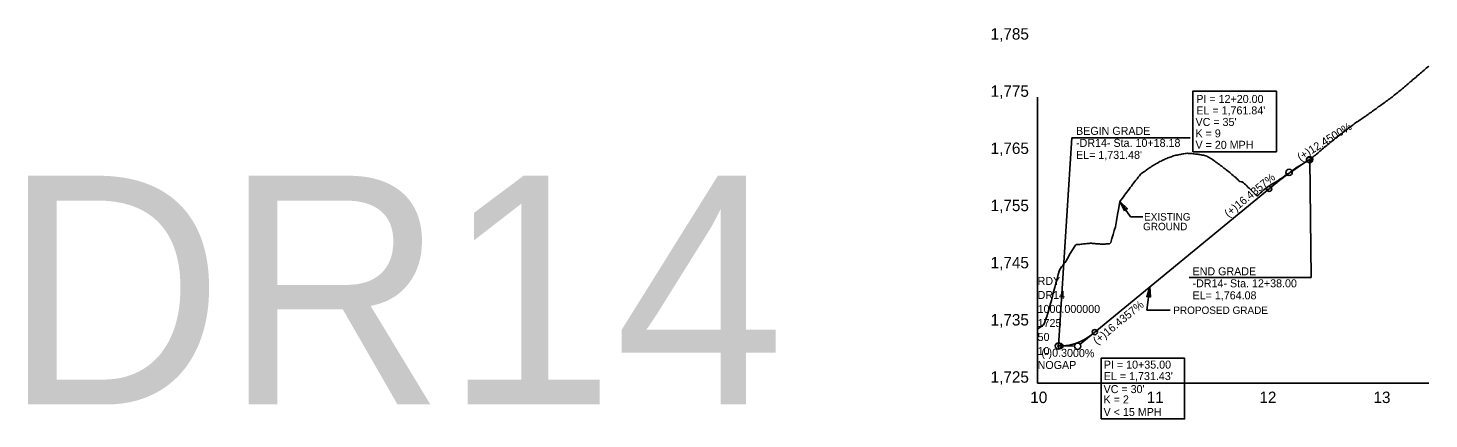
# Model space of a CAD drawing. Extents: x 498575 to 532350, y 405181 to 484585.
# Drawn here: x 526401 to 527626, y 452312 to 452654 of the extents above; entities that cross this region are included whole.
import ezdxf

# ---------------------------------------------------------------- set-up
doc = ezdxf.new("R2010")
doc.units = 0
for name, color, linetype in [('Exist Profile Cell', 7, 'Continuous'), ('Exist Vertical Profile Ground Line', 7, 'Continuous'), ('Exist Vertical Profile Horizontal Axis Label Major', 7, 'Continuous'), ('Exist Vertical Profile Vertical Axis Label', 7, 'Continuous'), ('Prop Grid Mask', 7, 'Continuous'), ('Prop PFL Text', 7, 'Continuous'), ('Prop Vertical Profile Curve Label', 7, 'Continuous'), ('Prop Vertical Profile Grade', 7, 'Continuous'), ('Prop Vertical Profile Grade Label', 7, 'Continuous'), ('Prop VPI Label', 7, 'Continuous'), ('Scratch_Level_7', 7, 'Continuous')]:
    doc.layers.add(name, color=color, linetype=linetype)

msp = doc.modelspace()

# ---------------------------------------------------------------- linework, layer by layer
at = {"layer": 'Exist Profile Cell'}
for q in [(527283.8, 452593.4), (527626.1, 452343.4), (527283.8, 452343.4)]:
    msp.add_line((527283.8, 452343.4), q, dxfattribs=at)
at = {"layer": 'Exist Vertical Profile Ground Line'}
for points in [[(527583.8, 452586.2), (527584.8, 452586.9), (527585.8, 452587.6), (527586.8, 452588.4), (527587.8, 452589.1), (527588.8, 452589.8), (527589.8, 452590.5), (527590.8, 452591.2), (527591.8, 452591.9), (527592.8, 452592.7), (527593.8, 452593.5), (527594.8, 452594.3), (527595.8, 452595.1), (527596.8, 452595.9), (527597.8, 452596.7), (527598.8, 452597.5), (527599.8, 452598.3), (527600.8, 452599.1), (527601.8, 452599.9), (527602.8, 452600.8), (527603.8, 452601.6), (527604.8, 452602.4), (527605.8, 452603.2), (527606.8, 452604.1), (527607.8, 452605), (527608.8, 452605.8), (527609.8, 452606.7), (527610.8, 452607.5), (527611.8, 452608.4), (527612.8, 452609.3), (527613.8, 452610.1), (527614.8, 452611), (527615.8, 452611.9), (527616.8, 452612.7), (527617.8, 452613.6), (527618.8, 452614.4), (527619.8, 452615.3), (527620.8, 452616.1), (527621.8, 452616.9), (527622.8, 452617.8), (527623.8, 452618.6), (527624.8, 452619.5), (527625.8, 452620.3), (527626.1, 452620.6)], [(527483.8, 452514), (527484.8, 452514.8), (527485.8, 452515.4), (527486.8, 452516), (527487.8, 452516.6), (527488.8, 452517.2), (527489.8, 452517.8), (527490.8, 452518.5), (527491.8, 452519.1), (527492.8, 452519.7), (527493.8, 452520.3), (527494.8, 452521), (527495.8, 452521.6), (527496.8, 452522.2), (527497.8, 452522.9), (527498.8, 452523.5), (527499.8, 452524.2), (527500.8, 452524.8), (527501.8, 452525.5), (527502.8, 452526.2), (527503.8, 452526.9), (527504.8, 452527.7), (527505.8, 452528.4), (527506.8, 452529.2), (527507.8, 452529.9), (527508.8, 452530.7), (527509.8, 452531.5), (527510.8, 452532.1), (527511.8, 452532.7), (527512.8, 452533.3), (527513.8, 452534), (527514.8, 452534.6), (527515.8, 452535.2), (527516.8, 452535.8), (527517.8, 452536.4), (527518.8, 452537), (527519.8, 452537.6), (527520.8, 452538.2), (527521.8, 452538.8), (527522.8, 452539.5), (527523.8, 452540.3), (527524.8, 452541.2), (527525.8, 452542), (527526.8, 452542.8), (527527.8, 452543.6), (527528.8, 452544.5), (527529.8, 452545.3), (527530.8, 452546.2), (527531.8, 452547.1), (527532.8, 452547.9), (527533.8, 452548.7), (527534.8, 452549.6), (527535.8, 452550.4), (527536.8, 452551.2), (527537.8, 452552), (527538.8, 452552.8), (527539.8, 452553.7), (527540.8, 452554.5), (527541.8, 452555.3), (527542.8, 452556.1), (527543.8, 452557), (527544.8, 452557.8), (527545.8, 452558.6), (527546.8, 452559.4), (527547.8, 452560.2), (527548.8, 452561), (527549.8, 452561.7), (527550.8, 452562.5), (527551.8, 452563.2), (527552.8, 452563.9), (527553.8, 452564.7), (527554.8, 452565.4), (527555.8, 452566.2), (527556.8, 452567), (527557.8, 452567.7), (527558.8, 452568.5), (527559.8, 452569.3), (527560.8, 452570.1), (527561.8, 452570.8), (527562.8, 452571.5), (527563.8, 452572.2), (527564.8, 452572.8), (527565.8, 452573.5), (527566.8, 452574.1), (527567.8, 452574.8), (527568.8, 452575.5), (527569.8, 452576.1), (527570.8, 452576.8), (527571.8, 452577.5), (527572.8, 452578.3), (527573.8, 452579), (527574.8, 452579.7), (527575.8, 452580.4), (527576.8, 452581.1), (527577.8, 452581.9), (527578.8, 452582.6), (527579.8, 452583.3), (527580.8, 452584), (527581.8, 452584.8), (527582.8, 452585.5), (527583.8, 452586.2)], [(527383.8, 452533), (527384.8, 452533.6), (527385.8, 452534.1), (527386.8, 452534.7), (527387.8, 452535.3), (527388.8, 452535.8), (527389.8, 452536.4), (527390.8, 452537), (527391.8, 452537.5), (527392.8, 452538), (527393.8, 452538.6), (527394.8, 452539), (527395.8, 452539.4), (527396.8, 452539.8), (527397.8, 452540.2), (527398.8, 452540.6), (527399.8, 452541), (527400.8, 452541.3), (527401.8, 452541.7), (527402.8, 452542), (527403.8, 452542.4), (527404.8, 452542.6), (527405.8, 452542.7), (527406.8, 452542.9), (527407.8, 452543.1), (527408.8, 452543.3), (527409.8, 452543.5), (527410.8, 452543.7), (527411.8, 452543.9), (527412.8, 452544), (527413.8, 452544.2), (527414.8, 452544.3), (527415.8, 452544.2), (527416.8, 452544.1), (527417.8, 452544.1), (527418.8, 452544), (527419.8, 452543.9), (527420.8, 452543.7), (527421.8, 452543.6), (527422.8, 452543.5), (527423.8, 452543.4), (527424.8, 452543.3), (527425.8, 452543.1), (527426.8, 452543), (527427.8, 452542.8), (527428.8, 452542.6), (527429.8, 452542.4), (527430.8, 452542.1), (527431.8, 452541.7), (527432.8, 452541.1), (527433.8, 452540.6), (527434.8, 452540), (527435.8, 452539.4), (527436.8, 452538.8), (527437.8, 452538.1), (527438.8, 452537.4), (527439.8, 452536.6), (527440.8, 452535.9), (527441.8, 452535.2), (527442.8, 452534.4), (527443.8, 452533.6), (527444.8, 452532.9), (527445.8, 452532.1), (527446.8, 452531.4), (527447.8, 452530.6), (527448.8, 452529.8), (527449.8, 452529.1), (527450.8, 452528.3), (527451.8, 452527.5), (527452.8, 452526.6), (527453.8, 452525.8), (527454.8, 452525), (527455.8, 452524.1), (527456.8, 452523.3), (527457.8, 452522.3), (527458.8, 452521.3), (527459.8, 452520.3), (527460.8, 452519.6), (527461.8, 452519.4), (527462.8, 452519.2), (527463.8, 452518.5), (527464.8, 452517.6), (527465.8, 452516.7), (527466.8, 452515.8), (527467.8, 452514.8), (527468.8, 452513.8), (527469.8, 452512.8), (527470.8, 452511.8), (527471.8, 452510.8), (527472.8, 452509.8), (527473.8, 452508.9), (527474.8, 452507.9), (527475.8, 452507), (527476.8, 452507.6), (527477.8, 452508.8), (527478.8, 452509.7), (527479.8, 452510.6), (527480.8, 452511.5), (527481.8, 452512.3), (527482.8, 452513.2), (527483.8, 452514)], [(527283.8, 452390.6), (527284.8, 452391.4), (527285.8, 452392.1), (527286.8, 452392.9), (527287.8, 452393.6), (527288.8, 452394.4), (527289.8, 452395.7), (527290.8, 452398.7), (527291.8, 452401.6), (527292.8, 452404.6), (527293.8, 452408.2), (527294.8, 452412), (527295.8, 452415.7), (527296.8, 452419.5), (527297.8, 452423.2), (527298.8, 452427), (527299.8, 452430.7), (527300.8, 452434.5), (527301.8, 452438.2), (527302.8, 452442), (527303.8, 452443.7), (527304.8, 452445), (527305.8, 452446.3), (527306.8, 452447.6), (527307.8, 452448.9), (527308.8, 452450.4), (527309.8, 452452.2), (527310.8, 452453.9), (527311.8, 452455.7), (527312.8, 452457.5), (527313.8, 452459.1), (527314.8, 452460.7), (527315.8, 452462.3), (527316.8, 452463.9), (527317.8, 452464.4), (527318.8, 452464.5), (527319.8, 452464.6), (527320.8, 452464.6), (527321.8, 452464.7), (527322.8, 452464.9), (527323.8, 452465), (527324.8, 452465.1), (527325.8, 452465.2), (527326.8, 452465.3), (527327.8, 452465.4), (527328.8, 452465.5), (527329.8, 452465.7), (527330.8, 452465.6), (527331.8, 452465.5), (527332.8, 452465.3), (527333.8, 452465.3), (527334.8, 452465.2), (527335.8, 452465.2), (527336.8, 452465.1), (527337.8, 452465), (527338.8, 452464.9), (527339.8, 452464.9), (527340.8, 452464.9), (527341.8, 452464.8), (527342.8, 452464.9), (527343.8, 452465), (527344.8, 452465.1), (527345.8, 452465.2), (527346.8, 452465.2), (527347.8, 452466.3), (527348.8, 452469.8), (527349.8, 452473.2), (527350.8, 452476.7), (527351.8, 452480.1), (527352.8, 452485.3), (527353.8, 452490.9), (527354.8, 452496.6), (527355.8, 452502.1), (527356.8, 452503.5), (527357.8, 452504.8), (527358.8, 452506.2), (527359.8, 452507.6), (527360.8, 452508.9), (527361.8, 452510.3), (527362.8, 452511.6), (527363.8, 452512.9), (527364.8, 452514.3), (527365.8, 452515.6), (527366.8, 452516.9), (527367.8, 452518.2), (527368.8, 452519.5), (527369.8, 452520.8), (527370.8, 452522.1), (527371.8, 452523.4), (527372.8, 452524.7), (527373.8, 452525.9), (527374.8, 452526.7), (527375.8, 452527.4), (527376.8, 452528.1), (527377.8, 452528.8), (527378.8, 452529.6), (527379.8, 452530.3), (527380.8, 452531), (527381.8, 452531.7), (527382.8, 452532.3), (527383.8, 452533)]]:
    msp.add_lwpolyline(points, dxfattribs=at)
at = {"layer": 'Prop Grid Mask'}
for points in [[(527419.7, 452545.6), (527492.7, 452545.6), (527492.7, 452598.7), (527419.7, 452598.7)], [(527339.3, 452312), (527412.3, 452312), (527412.3, 452365.1), (527339.3, 452365.1)]]:
    msp.add_lwpolyline(points, close=True, dxfattribs=at)
at = {"layer": 'Prop PFL Text'}
for p, q in [((527355.8, 452502.1), (527365.1, 452488.7)), ((527365.1, 452488.7), (527375.9, 452488.7)), ((527379.3, 452407.2), (527382.1, 452427.6)), ((527399.7, 452407.2), (527379.3, 452407.2))]:
    msp.add_line(p, q, dxfattribs=at)
for points in [[(527359.7, 452493.9), (527355.8, 452502.1), (527362.3, 452495.6), (527360.4, 452495.7)], [(527382.4, 452418.5), (527382.1, 452427.6), (527379.3, 452418.9), (527381, 452419.8)]]:
    msp.add_lwpolyline(points, close=True, dxfattribs=at)
at = {"layer": 'Prop Vertical Profile Curve Label'}
for centre in [(527521.3, 452538.5), (527486.3, 452513.2), (527333.8, 452387.9), (527303.8, 452375.8)]:
    msp.add_circle(centre, 2.25, dxfattribs=at)
at = {"layer": 'Prop Vertical Profile Grade'}
for p, q in [((527521.3, 452538.5), (527521.8, 452538.8)), ((527333.8, 452387.9), (527486.3, 452513.2)), ((527302, 452375.8), (527303.8, 452375.8))]:
    msp.add_line(p, q, dxfattribs=at)
for points in [[(527486.3, 452513.2), (527487, 452513.8), (527487.7, 452514.4), (527488.4, 452515), (527489.1, 452515.5), (527489.8, 452516.1), (527490.5, 452516.6), (527491.2, 452517.2), (527491.9, 452517.8), (527492.6, 452518.3), (527493.3, 452518.9), (527494, 452519.4), (527494.7, 452519.9), (527495.4, 452520.5), (527496.1, 452521), (527496.8, 452521.6), (527497.5, 452522.1), (527498.2, 452522.6), (527498.9, 452523.1), (527499.6, 452523.7), (527500.3, 452524.2), (527501, 452524.7), (527501.7, 452525.2), (527502.4, 452525.7), (527503.1, 452526.2), (527503.8, 452526.8), (527504.5, 452527.3), (527505.2, 452527.8), (527505.9, 452528.3), (527506.6, 452528.8), (527507.3, 452529.2), (527508, 452529.7), (527508.7, 452530.2), (527509.4, 452530.7), (527510.1, 452531.2), (527510.8, 452531.7), (527511.5, 452532.1), (527512.2, 452532.6), (527512.9, 452533.1), (527513.6, 452533.6), (527514.3, 452534), (527515, 452534.5), (527515.7, 452534.9), (527516.4, 452535.4), (527517.1, 452535.9), (527517.8, 452536.3), (527518.5, 452536.8), (527519.2, 452537.2), (527519.9, 452537.6), (527520.6, 452538.1), (527521.3, 452538.5)], [(527303.8, 452375.8), (527304.4, 452375.8), (527305, 452375.8), (527305.6, 452375.8), (527306.2, 452375.9), (527306.8, 452375.9), (527307.4, 452375.9), (527308, 452376), (527308.6, 452376.1), (527309.2, 452376.1), (527309.8, 452376.2), (527310.4, 452376.3), (527311, 452376.4), (527311.6, 452376.6), (527312.2, 452376.7), (527312.8, 452376.8), (527313.4, 452377), (527314, 452377.1), (527314.6, 452377.3), (527315.2, 452377.5), (527315.8, 452377.6), (527316.4, 452377.8), (527317, 452378.1), (527317.6, 452378.3), (527318.2, 452378.5), (527318.8, 452378.7), (527319.4, 452379), (527320, 452379.2), (527320.6, 452379.5), (527321.2, 452379.8), (527321.8, 452380.1), (527322.4, 452380.4), (527323, 452380.7), (527323.6, 452381), (527324.2, 452381.3), (527324.8, 452381.7), (527325.4, 452382), (527326, 452382.4), (527326.6, 452382.7), (527327.2, 452383.1), (527327.8, 452383.5), (527328.4, 452383.9), (527329, 452384.3), (527329.6, 452384.7), (527330.2, 452385.1), (527330.8, 452385.6), (527331.4, 452386), (527332, 452386.5), (527332.6, 452387), (527333.2, 452387.4), (527333.8, 452387.9)]]:
    msp.add_spline(points, degree=3, dxfattribs=at)
at = {"layer": 'Prop VPI Label'}
for p, q in [((527302, 452375.8), (527313.8, 452557.9)), ((527313.8, 452557.9), (527417.3, 452557.9)), ((527521.3, 452538.5), (527506.1, 452529.1)), ((527518.8, 452537), (527506.1, 452528.4)), ((527521.8, 452539), (527523, 452435.8)), ((527486.3, 452513.2), (527501.7, 452525.9)), ((527416.4, 452435.8), (527523, 452435.8)), ((527333.8, 452387.9), (527320.9, 452377.3)), ((527303.8, 452375.8), (527316, 452375.6))]:
    msp.add_line(p, q, dxfattribs=at)
for centre in [(527521.8, 452538.8), (527503.8, 452527.6), (527302, 452375.8), (527318.8, 452375.6)]:
    msp.add_circle(centre, 2.75, dxfattribs=at)

# ---------------------------------------------------------------- texts
at = {"layer": 'Exist Profile Cell'}
for s, p in [('RDY', (527283.8, 452429.2)), ('DR14', (527283.8, 452416.9)), ('1000.000000', (527283.8, 452404.7)), ('1725', (527283.8, 452392.4)), ('50', (527283.8, 452380.2)), ('10', (527283.8, 452367.9)), ('NOGAP', (527283.8, 452355.7))]:
    msp.add_text(s, height=7, dxfattribs=at).set_placement(p)
at = {"layer": 'Exist Vertical Profile Horizontal Axis Label Major'}
for s, p in [('10', (527277.4, 452325.9)), ('11', (527379.2, 452325.9)), ('12', (527477.8, 452325.9)), ('13', (527577.6, 452325.9))]:
    msp.add_text(s, height=10, dxfattribs=at).set_placement(p)
at = {"layer": 'Exist Vertical Profile Vertical Axis Label'}
for s, p in [('1,785', (527242.7, 452643.7)), ('1,775', (527242.7, 452593.7)), ('1,765', (527242.7, 452543.7)), ('1,755', (527242.7, 452493.7)), ('1,745', (527242.7, 452443.7)), ('1,735', (527242.7, 452393.7)), ('1,725', (527242.7, 452343.7))]:
    msp.add_text(s, height=10, dxfattribs=at).set_placement(p)
at = {"layer": 'Prop PFL Text'}
for s, height, p in [('EXISTING ', 6.52, (527376.9, 452485.5)), ('GROUND', 6.52, (527376, 452477)), ('PROPOSED GRADE', 6.516, (527402.5, 452403.8))]:
    msp.add_text(s, height=height, dxfattribs=at).set_placement(p)
at = {"layer": 'Prop Vertical Profile Curve Label'}
for s, p in [('V = 20 MPH ', (527421.9, 452548.2)), ("VC = 30'", (527341.5, 452334.6)), ('K = 2', (527341.5, 452325.6)), ('V < 15 MPH ', (527341.5, 452314.6))]:
    msp.add_text(s, height=7, dxfattribs=at).set_placement(p)
at = {"layer": 'Prop Vertical Profile Grade Label'}
for s, rotation, p in [('(+)12.4500%', 31.9023, (527513.6, 452537.3)), ('(+)16.4357%', 39.4129, (527450.7, 452487.9)), ('(+)16.4357%', 39.4129, (527335.8, 452376.6)), ('(-)0.3000%', 359.1406, (527287.1, 452366.6))]:
    msp.add_text(s, height=7, rotation=rotation, dxfattribs=at).set_placement(p)
at = {"layer": 'Prop VPI Label'}
for s, p in [('PI = 12+20.00', (527422.6, 452588.3)), ("EL = 1,761.84'", (527422.6, 452578.3)), ("VC = 35'", (527421.9, 452568.2)), ('BEGIN GRADE', (527317.4, 452560.4)), ('K = 9', (527421.9, 452558.2)), ('-DR14- Sta. 10+18.18', (527317.4, 452549.9)), ("EL= 1,731.48'", (527317.4, 452539.4)), ('END GRADE', (527419.3, 452437.6)), ('-DR14- Sta. 12+38.00', (527419.3, 452427.1)), ('EL= 1,764.08', (527419.3, 452416.6)), ('PI = 10+35.00', (527341.7, 452356)), ("EL = 1,731.43'", (527341.7, 452346))]:
    msp.add_text(s, height=7, dxfattribs=at).set_placement(p)
at = {"layer": 'Scratch_Level_7'}
msp.add_text('DR14', height=200, dxfattribs=at).set_placement((526378.7, 452324.7))

doc.saveas('drawing.dxf')
